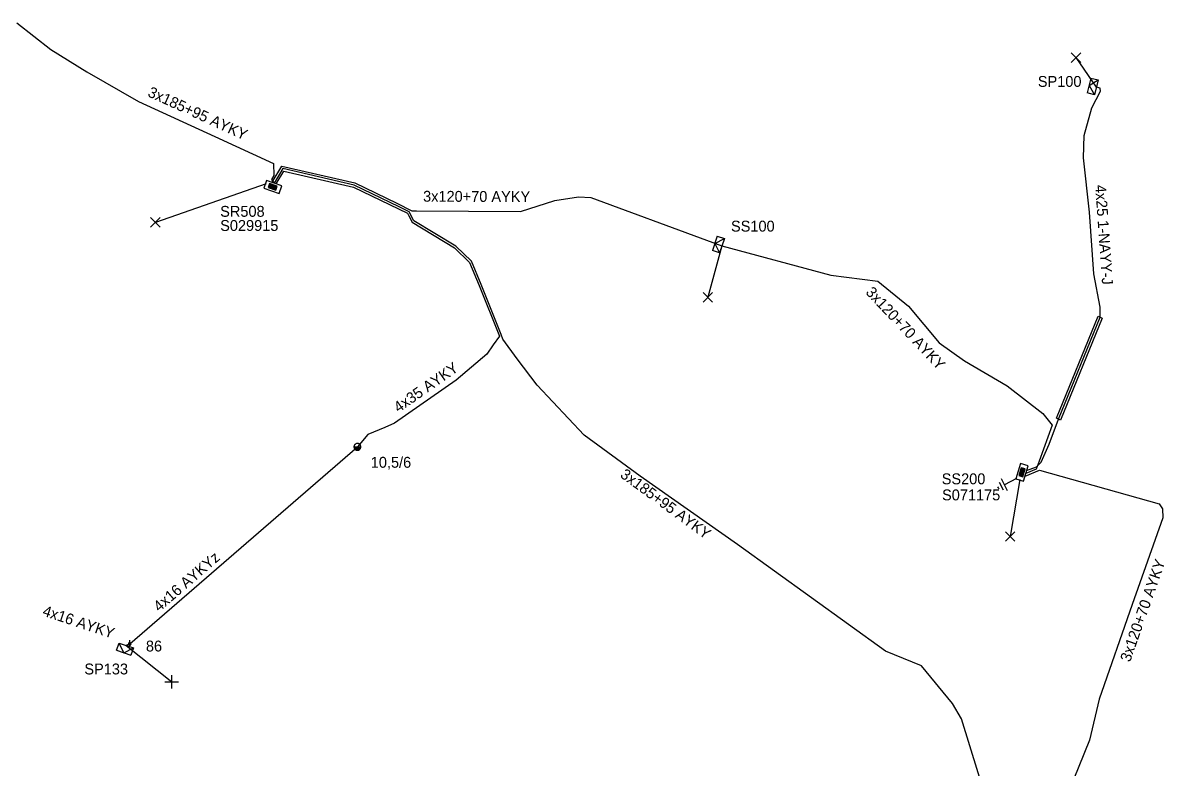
# Model space of a CAD drawing. Extents: x -788458 to -786145, y -1154772 to -1152372.
# Drawn here: x -787355.9 to -787251, y -1153175.6 to -1153107.1 of the extents above; entities that cross this region are included whole.
import ezdxf

# ---------------------------------------------------------------- set-up
doc = ezdxf.new("R2010")
doc.units = 0
for name, color, linetype in [('Vrstva 1', 7, 'Continuous'), ('Vrstva 12', 7, 'Continuous'), ('Vrstva 13', 7, 'Continuous'), ('Vrstva 14', 7, 'Continuous'), ('Vrstva 15', 7, 'Continuous'), ('Vrstva 2', 7, 'Continuous'), ('Vrstva 20', 7, 'Continuous'), ('Vrstva 28', 7, 'Continuous'), ('Vrstva 29', 7, 'Continuous'), ('Vrstva 30', 7, 'Continuous'), ('Vrstva 31', 7, 'Continuous'), ('Vrstva 33', 7, 'Continuous'), ('Vrstva 34', 7, 'Continuous'), ('Vrstva 5', 7, 'Continuous'), ('Vrstva 52', 7, 'Continuous'), ('Vrstva 53', 7, 'Continuous'), ('Vrstva 54', 7, 'Continuous'), ('Vrstva 59', 7, 'Continuous'), ('Vrstva 6', 7, 'Continuous'), ('Vrstva 8', 7, 'Continuous'), ('Vrstva 9', 7, 'Continuous')]:
    doc.layers.add(name, color=color, linetype=linetype)

# ---------------------------------------------------------------- blocks, each defined once
blk = doc.blocks.new('NN440')
at = {"layer": 'Vrstva 2'}
for points in [[(0.63, 0), (0.63, 0.06), (0.62, 0.13), (0.6, 0.19), (0.58, 0.25), (0.55, 0.31), (0.51, 0.37), (0.47, 0.42), (0.42, 0.46), (0.37, 0.51), (0.32, 0.54), (0.26, 0.57), (0.2, 0.59), (0.13, 0.61), (0.07, 0.62), (0, 0.63), (-0.06, 0.62), (-0.13, 0.61), (-0.19, 0.59), (-0.26, 0.57), (-0.31, 0.54), (-0.37, 0.51), (-0.42, 0.46), (-0.47, 0.42), (-0.51, 0.37), (-0.54, 0.31), (-0.57, 0.25), (-0.6, 0.19), (-0.62, 0.13), (-0.63, 0.06), (-0.63, 0), (-0.63, -0.07), (-0.62, -0.14), (-0.6, -0.2), (-0.57, -0.26), (-0.54, -0.32), (-0.51, -0.37), (-0.47, -0.43), (-0.42, -0.47), (-0.37, -0.51), (-0.31, -0.55), (-0.26, -0.58), (-0.19, -0.6), (-0.13, -0.62), (-0.06, -0.63), (0, -0.63), (0.07, -0.63), (0.13, -0.62), (0.2, -0.6), (0.26, -0.58), (0.32, -0.55), (0.37, -0.51), (0.42, -0.47), (0.47, -0.43), (0.51, -0.37), (0.55, -0.32), (0.58, -0.26), (0.6, -0.2), (0.62, -0.14), (0.63, -0.07), (0.63, 0)], [(-0.63, 0), (0.63, 0)], [(-0.6, -0.18), (0.57, -0.18)], [(-0.51, -0.32), (0.5, -0.32)], [(-0.37, -0.47), (0.35, -0.47)]]:
    blk.add_lwpolyline(points, dxfattribs=at)
blk = doc.blocks.new('NN800')
at = {"layer": 'Vrstva 1'}
for points in [[(-0.44, 0.44), (0.44, -0.44)], [(-0.44, -0.44), (0.44, 0.44)]]:
    blk.add_lwpolyline(points, dxfattribs=at)
blk = doc.blocks.new('NN620')
at = {"layer": 'Vrstva 8'}
for points in [[(0.75, 0), (-0.75, 0)], [(-0.75, 0), (-0.75, -0.75)], [(0.75, -0.75), (0.75, 0)], [(-0.75, -0.75), (0.75, -0.75)], [(0.37, -0.18), (-0.38, -0.18)], [(-0.38, -0.18), (-0.38, -0.56)], [(-0.38, -0.56), (0.37, -0.56)], [(0.32, -0.23), (-0.33, -0.23)], [(-0.33, -0.23), (-0.33, -0.51)], [(-0.33, -0.51), (0.32, -0.51)], [(0.27, -0.27), (-0.28, -0.27)], [(-0.28, -0.27), (-0.28, -0.46)], [(-0.28, -0.46), (0.27, -0.46)], [(0.23, -0.32), (-0.23, -0.32)], [(-0.23, -0.32), (-0.23, -0.42)], [(-0.23, -0.42), (0.23, -0.42)], [(-0.19, -0.37), (0.19, -0.37)], [(0.23, -0.42), (0.23, -0.32)], [(0.27, -0.46), (0.27, -0.27)], [(0.32, -0.51), (0.32, -0.23)], [(0.37, -0.56), (0.37, -0.18)]]:
    blk.add_lwpolyline(points, dxfattribs=at)
blk = doc.blocks.new('NN630')
at = {"layer": 'Vrstva 9'}
for points in [[(0, -0.7), (-0.7, 0)], [(-0.7, -0.7), (-0.7, 0), (0.7, 0), (0.7, -0.7)], [(-0.7, -0.7), (0.7, -0.7)], [(0, -0.7), (0.7, 0)]]:
    blk.add_lwpolyline(points, dxfattribs=at)
blk = doc.blocks.new('NN810')
at = {"layer": 'Vrstva 14'}
for points in [[(0, -0.64), (0, -1.89)], [(0.63, -1.89), (-0.62, -1.89)], [(0.39, -2.2), (-0.4, -2.2)], [(0, -2.52), (-0.12, -2.52)], [(0.14, -2.52), (0, -2.52)]]:
    blk.add_lwpolyline(points, dxfattribs=at)
blk = doc.blocks.new('NN500')
at = {"layer": 'Vrstva 2'}
for points in [[(0, -0.24), (0.02, -0.23), (0.05, -0.23), (0.07, -0.22), (0.09, -0.22), (0.12, -0.2), (0.14, -0.19), (0.16, -0.18), (0.17, -0.16), (0.19, -0.14), (0.2, -0.12), (0.21, -0.1), (0.22, -0.07), (0.23, -0.05), (0.23, -0.02), (0.23, 0), (0.23, 0.02), (0.23, 0.05), (0.22, 0.07), (0.21, 0.1), (0.2, 0.12), (0.19, 0.14), (0.17, 0.16), (0.16, 0.17), (0.14, 0.19), (0.12, 0.2), (0.09, 0.21), (0.07, 0.22), (0.05, 0.23), (0.02, 0.23), (0, 0.23), (-0.03, 0.23), (-0.05, 0.23), (-0.07, 0.22), (-0.1, 0.21), (-0.12, 0.2), (-0.14, 0.19), (-0.16, 0.17), (-0.18, 0.16), (-0.19, 0.14), (-0.2, 0.12), (-0.22, 0.1), (-0.22, 0.07), (-0.23, 0.05), (-0.23, 0.02), (-0.24, 0), (-0.23, -0.02), (-0.23, -0.05), (-0.22, -0.07), (-0.22, -0.1), (-0.2, -0.12), (-0.19, -0.14), (-0.18, -0.16), (-0.16, -0.18), (-0.14, -0.19), (-0.12, -0.2), (-0.1, -0.22), (-0.07, -0.22), (-0.05, -0.23), (-0.03, -0.23), (0, -0.24)], [(0, -0.24), (0.02, -0.23), (0.05, -0.23), (0.07, -0.22), (0.09, -0.22), (0.12, -0.2), (0.14, -0.19), (0.16, -0.18), (0.17, -0.16), (0.19, -0.14), (0.2, -0.12), (0.21, -0.1), (0.22, -0.07), (0.23, -0.05), (0.23, -0.02), (0.23, 0), (0.23, 0.02), (0.23, 0.05), (0.22, 0.07), (0.21, 0.1), (0.2, 0.12), (0.19, 0.14), (0.17, 0.16), (0.16, 0.17), (0.14, 0.19), (0.12, 0.2), (0.09, 0.21), (0.07, 0.22), (0.05, 0.23), (0.02, 0.23), (0, 0.23), (-0.03, 0.23), (-0.05, 0.23), (-0.07, 0.22), (-0.1, 0.21), (-0.12, 0.2), (-0.14, 0.19), (-0.16, 0.17), (-0.18, 0.16), (-0.19, 0.14), (-0.2, 0.12), (-0.22, 0.1), (-0.22, 0.07), (-0.23, 0.05), (-0.23, 0.02), (-0.24, 0), (-0.23, -0.02), (-0.23, -0.05), (-0.22, -0.07), (-0.22, -0.1), (-0.2, -0.12), (-0.19, -0.14), (-0.18, -0.16), (-0.16, -0.18), (-0.14, -0.19), (-0.12, -0.2), (-0.1, -0.22), (-0.07, -0.22), (-0.05, -0.23), (-0.03, -0.23), (0, -0.24)], [(0, -0.21), (0.02, -0.2), (0.04, -0.2), (0.06, -0.2), (0.08, -0.19), (0.1, -0.18), (0.12, -0.17), (0.14, -0.15), (0.15, -0.14), (0.16, -0.12), (0.18, -0.1), (0.19, -0.08), (0.19, -0.06), (0.2, -0.04), (0.2, -0.02), (0.2, 0), (0.2, 0.02), (0.2, 0.04), (0.19, 0.06), (0.19, 0.08), (0.18, 0.1), (0.16, 0.12), (0.15, 0.14), (0.14, 0.15), (0.12, 0.17), (0.1, 0.18), (0.08, 0.19), (0.06, 0.19), (0.04, 0.2), (0.02, 0.2), (0, 0.2), (-0.02, 0.2), (-0.04, 0.2), (-0.06, 0.19), (-0.08, 0.19), (-0.1, 0.18), (-0.12, 0.17), (-0.14, 0.15), (-0.15, 0.14), (-0.17, 0.12), (-0.18, 0.1), (-0.19, 0.08), (-0.2, 0.06), (-0.2, 0.04), (-0.21, 0.02), (-0.21, 0), (-0.21, -0.02), (-0.2, -0.04), (-0.2, -0.06), (-0.19, -0.08), (-0.18, -0.1), (-0.17, -0.12), (-0.15, -0.14), (-0.14, -0.15), (-0.12, -0.17), (-0.1, -0.18), (-0.08, -0.19), (-0.06, -0.2), (-0.04, -0.2), (-0.02, -0.2), (0, -0.21)], [(0, -0.18), (0.02, -0.18), (0.04, -0.17), (0.05, -0.17), (0.07, -0.16), (0.09, -0.15), (0.1, -0.14), (0.12, -0.13), (0.13, -0.12), (0.14, -0.1), (0.15, -0.09), (0.16, -0.07), (0.17, -0.05), (0.17, -0.04), (0.17, -0.02), (0.17, 0), (0.17, 0.02), (0.17, 0.04), (0.17, 0.05), (0.16, 0.07), (0.15, 0.09), (0.14, 0.1), (0.13, 0.12), (0.12, 0.13), (0.1, 0.14), (0.09, 0.15), (0.07, 0.16), (0.05, 0.17), (0.04, 0.17), (0.02, 0.17), (0, 0.18), (-0.02, 0.17), (-0.04, 0.17), (-0.06, 0.17), (-0.07, 0.16), (-0.09, 0.15), (-0.1, 0.14), (-0.12, 0.13), (-0.13, 0.12), (-0.14, 0.1), (-0.15, 0.09), (-0.16, 0.07), (-0.17, 0.05), (-0.17, 0.04), (-0.18, 0.02), (-0.18, 0), (-0.18, -0.02), (-0.17, -0.04), (-0.17, -0.05), (-0.16, -0.07), (-0.15, -0.09), (-0.14, -0.1), (-0.13, -0.12), (-0.12, -0.13), (-0.1, -0.14), (-0.09, -0.15), (-0.07, -0.16), (-0.06, -0.17), (-0.04, -0.17), (-0.02, -0.18), (0, -0.18)], [(0, -0.15), (0.01, -0.15), (0.03, -0.14), (0.04, -0.14), (0.06, -0.13), (0.07, -0.13), (0.08, -0.12), (0.1, -0.11), (0.11, -0.1), (0.12, -0.09), (0.13, -0.07), (0.13, -0.06), (0.14, -0.05), (0.14, -0.03), (0.14, -0.02), (0.14, 0), (0.14, 0.01), (0.14, 0.03), (0.14, 0.04), (0.13, 0.06), (0.13, 0.07), (0.12, 0.09), (0.11, 0.1), (0.1, 0.11), (0.08, 0.12), (0.07, 0.13), (0.06, 0.13), (0.04, 0.14), (0.03, 0.14), (0.01, 0.14), (0, 0.15), (-0.02, 0.14), (-0.03, 0.14), (-0.05, 0.14), (-0.06, 0.13), (-0.07, 0.13), (-0.09, 0.12), (-0.1, 0.11), (-0.11, 0.1), (-0.12, 0.09), (-0.13, 0.07), (-0.13, 0.06), (-0.14, 0.04), (-0.14, 0.03), (-0.15, 0.01), (-0.15, 0), (-0.15, -0.02), (-0.14, -0.03), (-0.14, -0.05), (-0.13, -0.06), (-0.13, -0.07), (-0.12, -0.09), (-0.11, -0.1), (-0.1, -0.11), (-0.09, -0.12), (-0.07, -0.13), (-0.06, -0.13), (-0.05, -0.14), (-0.03, -0.14), (-0.02, -0.15), (0, -0.15)], [(0, -0.12), (0.01, -0.12), (0.02, -0.11), (0.03, -0.11), (0.05, -0.11), (0.06, -0.1), (0.07, -0.09), (0.08, -0.09), (0.09, -0.08), (0.09, -0.07), (0.1, -0.06), (0.11, -0.05), (0.11, -0.04), (0.11, -0.02), (0.11, -0.01), (0.12, 0), (0.11, 0.01), (0.11, 0.02), (0.11, 0.04), (0.11, 0.05), (0.1, 0.06), (0.09, 0.07), (0.09, 0.08), (0.08, 0.09), (0.07, 0.09), (0.06, 0.1), (0.05, 0.11), (0.03, 0.11), (0.02, 0.11), (0.01, 0.12), (0, 0.12), (-0.01, 0.12), (-0.03, 0.11), (-0.04, 0.11), (-0.05, 0.11), (-0.06, 0.1), (-0.07, 0.09), (-0.08, 0.09), (-0.09, 0.08), (-0.1, 0.07), (-0.1, 0.06), (-0.11, 0.05), (-0.11, 0.04), (-0.12, 0.02), (-0.12, 0.01), (-0.12, 0), (-0.12, -0.01), (-0.12, -0.02), (-0.11, -0.04), (-0.11, -0.05), (-0.1, -0.06), (-0.1, -0.07), (-0.09, -0.08), (-0.08, -0.09), (-0.07, -0.09), (-0.06, -0.1), (-0.05, -0.11), (-0.04, -0.11), (-0.03, -0.11), (-0.01, -0.12), (0, -0.12)], [(0, -0.09), (0.01, -0.09), (0.02, -0.09), (0.03, -0.08), (0.03, -0.08), (0.04, -0.08), (0.05, -0.07), (0.06, -0.07), (0.06, -0.06), (0.07, -0.05), (0.07, -0.04), (0.08, -0.04), (0.08, -0.03), (0.08, -0.02), (0.09, -0.01), (0.09, 0), (0.09, 0.01), (0.08, 0.02), (0.08, 0.03), (0.08, 0.03), (0.07, 0.04), (0.07, 0.05), (0.06, 0.06), (0.06, 0.06), (0.05, 0.07), (0.04, 0.07), (0.03, 0.08), (0.03, 0.08), (0.02, 0.08), (0.01, 0.09), (0, 0.09), (-0.01, 0.09), (-0.02, 0.08), (-0.03, 0.08), (-0.04, 0.08), (-0.04, 0.07), (-0.05, 0.07), (-0.06, 0.06), (-0.07, 0.06), (-0.07, 0.05), (-0.08, 0.04), (-0.08, 0.03), (-0.08, 0.03), (-0.09, 0.02), (-0.09, 0.01), (-0.09, 0), (-0.09, -0.01), (-0.09, -0.02), (-0.08, -0.03), (-0.08, -0.04), (-0.08, -0.04), (-0.07, -0.05), (-0.07, -0.06), (-0.06, -0.07), (-0.05, -0.07), (-0.04, -0.08), (-0.04, -0.08), (-0.03, -0.08), (-0.02, -0.09), (-0.01, -0.09), (0, -0.09)], [(0, -0.06), (0, -0.06), (0.01, -0.06), (0.02, -0.05), (0.02, -0.05), (0.03, -0.05), (0.03, -0.05), (0.04, -0.04), (0.04, -0.04), (0.05, -0.03), (0.05, -0.03), (0.05, -0.02), (0.05, -0.02), (0.05, -0.01), (0.06, -0.01), (0.06, 0), (0.06, 0.01), (0.05, 0.01), (0.05, 0.02), (0.05, 0.02), (0.05, 0.03), (0.05, 0.03), (0.04, 0.04), (0.04, 0.04), (0.03, 0.05), (0.03, 0.05), (0.02, 0.05), (0.02, 0.05), (0.01, 0.06), (0, 0.06), (0, 0.06), (-0.01, 0.06), (-0.01, 0.06), (-0.02, 0.05), (-0.02, 0.05), (-0.03, 0.05), (-0.03, 0.05), (-0.04, 0.04), (-0.04, 0.04), (-0.05, 0.03), (-0.05, 0.03), (-0.05, 0.02), (-0.06, 0.02), (-0.06, 0.01), (-0.06, 0.01), (-0.06, 0), (-0.06, -0.01), (-0.06, -0.01), (-0.06, -0.02), (-0.05, -0.02), (-0.05, -0.03), (-0.05, -0.03), (-0.04, -0.04), (-0.04, -0.04), (-0.03, -0.05), (-0.03, -0.05), (-0.02, -0.05), (-0.02, -0.05), (-0.01, -0.06), (-0.01, -0.06), (0, -0.06)], [(0, -0.03), (0, -0.03), (0, -0.03), (0.01, -0.03), (0.01, -0.03), (0.01, -0.02), (0.02, -0.02), (0.02, -0.02), (0.02, -0.02), (0.02, -0.02), (0.02, -0.01), (0.02, -0.01), (0.03, -0.01), (0.03, -0.01), (0.03, 0), (0.03, 0), (0.03, 0), (0.03, 0.01), (0.03, 0.01), (0.02, 0.01), (0.02, 0.01), (0.02, 0.02), (0.02, 0.02), (0.02, 0.02), (0.02, 0.02), (0.01, 0.02), (0.01, 0.02), (0.01, 0.03), (0, 0.03), (0, 0.03), (0, 0.03), (0, 0.03), (-0.01, 0.03), (-0.01, 0.03), (-0.01, 0.02), (-0.02, 0.02), (-0.02, 0.02), (-0.02, 0.02), (-0.02, 0.02), (-0.02, 0.02), (-0.03, 0.01), (-0.03, 0.01), (-0.03, 0.01), (-0.03, 0.01), (-0.03, 0), (-0.03, 0), (-0.03, 0), (-0.03, -0.01), (-0.03, -0.01), (-0.03, -0.01), (-0.03, -0.01), (-0.02, -0.02), (-0.02, -0.02), (-0.02, -0.02), (-0.02, -0.02), (-0.02, -0.02), (-0.01, -0.03), (-0.01, -0.03), (-0.01, -0.03), (0, -0.03), (0, -0.03)], [(0.23, 0), (0.7, 0)]]:
    blk.add_lwpolyline(points, dxfattribs=at)

msp = doc.modelspace()

# ---------------------------------------------------------------- linework, layer by layer
at = {"layer": 'Vrstva 20'}
msp.add_lwpolyline([(-787260.88, -1153143.51), (-787257.03, -1153134.13), (-787256.66, -1153134.29), (-787260.51, -1153143.67)], close=True, dxfattribs=at)
at = {"layer": 'Vrstva 5'}
for points in [[(-787356.49, -1153107.14), (-787353.37, -1153109.59), (-787350.04, -1153111.66), (-787345.31, -1153114.38), (-787338.27, -1153117.59), (-787332.9, -1153120.09), (-787332.86, -1153121.19), (-787333.07, -1153121.54), (-787332.83, -1153121.88)], [(-787263.64, -1153148.31), (-787262.71, -1153147.99), (-787262.27, -1153147.56), (-787261.54, -1153145.9), (-787260.7, -1153143.59), (-787256.85, -1153134.21), (-787256.85, -1153133.28), (-787257.45, -1153130.23), (-787257.85, -1153124.55), (-787258.39, -1153119.57), (-787258.33, -1153117.51), (-787257.63, -1153114.95), (-787256.83, -1153113.42), (-787256.85, -1153113.14), (-787257.2, -1153113.07)], [(-787333.01, -1153121.8), (-787332.13, -1153120.31), (-787325.39, -1153121.87), (-787321.54, -1153123.74), (-787320.16, -1153124.44), (-787319.72, -1153124.44), (-787310.17, -1153124.48), (-787307.02, -1153123.47), (-787304.82, -1153123.13), (-787303.69, -1153123.22), (-787293.06, -1153127.12), (-787291.64, -1153127.64), (-787281.64, -1153130.36), (-787277.3, -1153130.89), (-787274.49, -1153133.2), (-787271.67, -1153136.57), (-787269.33, -1153138.23), (-787265.41, -1153140.52), (-787262.13, -1153143.07), (-787261.28, -1153144.13), (-787262.48, -1153147.46), (-787262.75, -1153148.2), (-787263.69, -1153148.59)], [(-787267.32, -1153178.6), (-787269.61, -1153171.16), (-787270.45, -1153169.75), (-787273.3, -1153166.29), (-787276.61, -1153164.92), (-787290.2, -1153155.13), (-787299.15, -1153148.82), (-787304.3, -1153145.05), (-787308.64, -1153140.47), (-787310.47, -1153138.04), (-787311.78, -1153136.23), (-787311.95, -1153135.82), (-787313.78, -1153131.21), (-787314.69, -1153129.07), (-787316.11, -1153127.67), (-787319.97, -1153125.34), (-787320.41, -1153124.51), (-787321.34, -1153124.06), (-787325.46, -1153122.06), (-787332.03, -1153120.54), (-787332.83, -1153121.88)], [(-787332.63, -1153121.95), (-787331.93, -1153120.77), (-787325.53, -1153122.25), (-787320.57, -1153124.66), (-787320.43, -1153124.9), (-787320.13, -1153125.48), (-787316.23, -1153127.83), (-787314.85, -1153129.19), (-787313.96, -1153131.29), (-787312.11, -1153135.96), (-787312.69, -1153136.77), (-787313.28, -1153137.6), (-787316.1, -1153140), (-787321.77, -1153143.97), (-787322.66, -1153144.35), (-787324.21, -1153145.01), (-787325.17, -1153146.14)], [(-787263.76, -1153148.84), (-787262.44, -1153148.29), (-787251.42, -1153151.37), (-787251.12, -1153151.83), (-787251.09, -1153152.68), (-787253.92, -1153160.64), (-787256.95, -1153169.35), (-787257.83, -1153173.11), (-787259.79, -1153177.96), (-787262.36, -1153183.46), (-787264.41, -1153186.89), (-787264.39, -1153191.15), (-787263.83, -1153203.14), (-787264.21, -1153209.16), (-787264.8, -1153209.64), (-787265.63, -1153209.44)]]:
    msp.add_lwpolyline(points, dxfattribs=at)
at = {"layer": 'Vrstva 52'}
for points in [[(-787346.11, -1153164.26), (-787325.17, -1153146.14)], [(-787346.11, -1153164.26), (-787346.43, -1153164.41)]]:
    msp.add_lwpolyline(points, dxfattribs=at)
at = {"layer": 'Vrstva 59'}
for points in [[(-787257.2, -1153113.07), (-787259.07, -1153110.34)], [(-787333.57, -1153121.96), (-787343.75, -1153125.5)], [(-787291.64, -1153127.64), (-787292.94, -1153132.38)], [(-787264.25, -1153149.13), (-787265.13, -1153154.38)], [(-787346.43, -1153164.41), (-787342.25, -1153167.75)]]:
    msp.add_lwpolyline(points, dxfattribs=at)

# ---------------------------------------------------------------- block references
at = {"layer": 'Vrstva 13', "xscale": 0.5, "yscale": 0.5}
msp.add_blockref('NN440', (-787325.17, -1153146.14), dxfattribs=at)
at = {"layer": 'Vrstva 13', "xscale": 0.5, "yscale": 0.5, "rotation": 90}
msp.add_blockref('NN500', (-787346.11, -1153164.26), dxfattribs=at)
at = {"layer": 'Vrstva 15', "rotation": -62.44696380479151}
msp.add_blockref('NN810', (-787263.98, -1153148.75), dxfattribs=at)
at = {"layer": 'Vrstva 28'}
for p, rotation in [((-787332.83, -1153121.88), -18.529861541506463), ((-787263.69, -1153148.59), -106.56436737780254)]:
    msp.add_blockref('NN620', p, dxfattribs=dict(at, rotation=rotation))
at = {"layer": 'Vrstva 31'}
for p, rotation in [((-787257.2, -1153113.07), -103.82573400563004), ((-787291.64, -1153127.64), -108.24791219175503), ((-787346.43, -1153164.41), -18.828947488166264)]:
    msp.add_blockref('NN630', p, dxfattribs=dict(at, rotation=rotation))
at = {"layer": 'Vrstva 34'}
for p in [(-787259.07, -1153110.34), (-787343.75, -1153125.5), (-787292.94, -1153132.38), (-787265.13, -1153154.38)]:
    msp.add_blockref('NN800', p, dxfattribs=at)
at = {"layer": 'Vrstva 34', "rotation": 45}
msp.add_blockref('NN800', (-787342.25, -1153167.75), dxfattribs=at)

# ---------------------------------------------------------------- texts
at = {"layer": 'Vrstva 12'}
msp.add_text('10,5/6', height=1, dxfattribs=at).set_placement((-787323.94, -1153148.06))
at = {"layer": 'Vrstva 14'}
msp.add_text('86', height=1, dxfattribs=at).set_placement((-787344.62, -1153164.96))
at = {"layer": 'Vrstva 29'}
for s, p in [('S029915', (-787337.79, -1153126.28)), ('S071175', (-787271.4, -1153151.06))]:
    msp.add_text(s, height=1, dxfattribs=at).set_placement(p)
at = {"layer": 'Vrstva 30'}
for s, p in [('SR508', (-787337.79, -1153124.98)), ('SS200', (-787271.43, -1153149.58))]:
    msp.add_text(s, height=1, dxfattribs=at).set_placement(p)
at = {"layer": 'Vrstva 33'}
for s, p in [('SP100', (-787262.59, -1153113.03)), ('SS100', (-787290.81, -1153126.34)), ('SP133', (-787350.28, -1153167.07))]:
    msp.add_text(s, height=1, dxfattribs=at).set_placement(p)
at = {"layer": 'Vrstva 53'}
msp.add_text('4x16 AYKYz', height=1, rotation=40.871, dxfattribs=at).set_placement((-787343.4, -1153161.36))
at = {"layer": 'Vrstva 54'}
msp.add_text('4x16 AYKY', height=1, rotation=341.712, dxfattribs=at).set_placement((-787354.2, -1153161.64))
at = {"layer": 'Vrstva 6'}
for s, rotation, p in [('3x185+95 AYKY', 335.489, (-787344.53, -1153113.87)), ('3x120+70 AYKY', 359.779, (-787319.13, -1153123.59)), ('4x25 1-NAYY-J', 274.028, (-787257.32, -1153122.07)), ('3x120+70 AYKY', 313.29, (-787278.49, -1153131.98)), ('4x35 AYKY', 34.999, (-787321.39, -1153143.03)), ('3x185+95 AYKY', 323.794, (-787301.08, -1153148.87)), ('3x120+70 AYKY', 70.599, (-787254.11, -1153165.99))]:
    msp.add_text(s, height=1, rotation=rotation, dxfattribs=at).set_placement(p)

doc.saveas('drawing.dxf')
